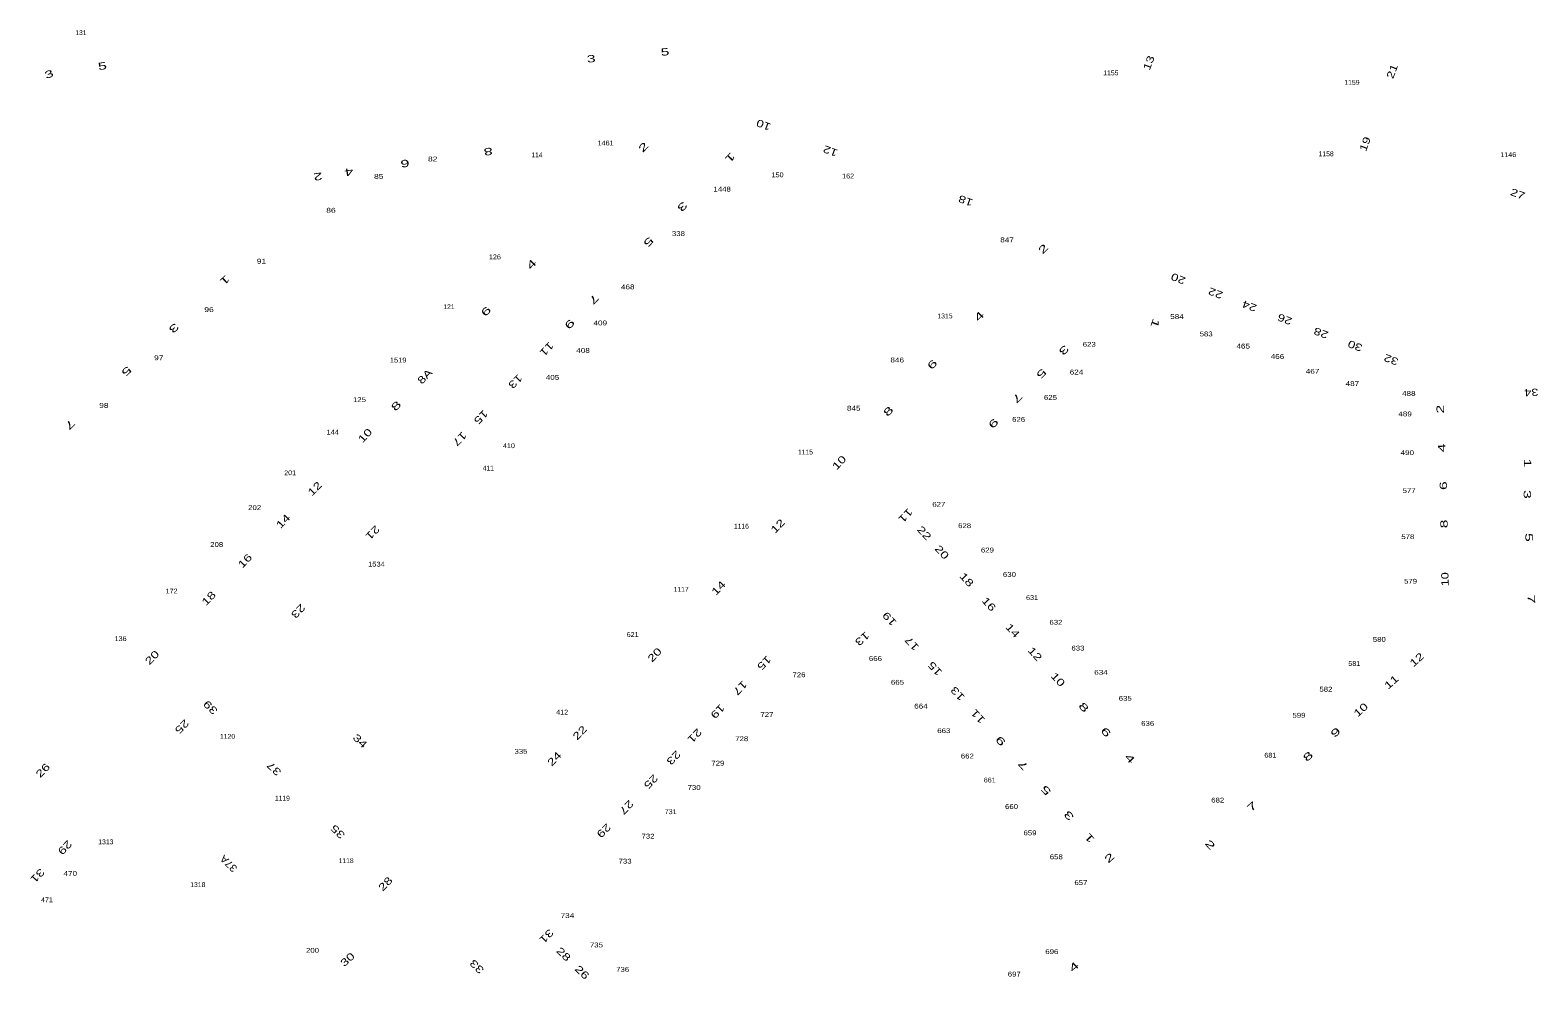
# Model space of a CAD drawing. Extents: x -828673 to -815583, y -1077737 to -1063807.
# Drawn here: x -819548.1 to -819237.8, y -1069104.1 to -1068908.7 of the extents above; entities that cross this region are included whole.
import ezdxf
from ezdxf.enums import TextEntityAlignment as Align

# ---------------------------------------------------------------- set-up
doc = ezdxf.new("R2010")
doc.units = 0
doc.header["$LTSCALE"] = 0.4
doc.layers.add('1', color=7, linetype='Continuous')
doc.layers.add('2', color=7, linetype='Continuous')

msp = doc.modelspace()

# ---------------------------------------------------------------- texts
at = {"layer": '1'}
for s, p in [('131', (-819537.617, -1068909.747)), ('114', (-819443.78, -1068934.925)), ('121', (-819461.888, -1068966.194)), ('1115', (-819388.525, -1068996.117)), ('411', (-819453.794, -1068999.429)), ('1116', (-819401.717, -1069011.39)), ('1117', (-819414.11, -1069024.403)), ('1119', (-819496.165, -1069067.403)), ('1118', (-819483.043, -1069080.264))]:
    msp.add_text(s, height=1, dxfattribs=at).set_placement(p, align=Align.CENTER)
for s, width, p in [('1155', 1.05, (-819325.699, -1068918.037)), ('1159', 1.05, (-819276.089, -1068919.989)), ('1461', 1.1, (-819429.658, -1068932.476)), ('82', 1.3, (-819465.237, -1068935.77)), ('1158', 1.05, (-819281.404, -1068934.699)), ('1146', 1.1, (-819243.927, -1068934.868)), ('85', 1.3, (-819476.337, -1068939.359)), ('150', 1.1, (-819394.274, -1068939.026)), ('162', 1.1, (-819379.763, -1068939.277)), ('1448', 1.2, (-819405.677, -1068941.98)), ('86', 1.3, (-819486.171, -1068946.327)), ('338', 1.2, (-819414.676, -1068951.136)), ('847', 1.25, (-819347.062, -1068952.43)), ('91', 1.3, (-819500.461, -1068956.814)), ('126', 1.1, (-819452.434, -1068955.932)), ('468', 1.25, (-819425.104, -1068962.104)), ('96', 1.3, (-819511.261, -1068966.78)), ('409', 1.25, (-819430.75, -1068969.532)), ('1315', 1.05, (-819359.837, -1068968.094)), ('584', 1.25, (-819312.093, -1068968.217)), ('583', 1.2, (-819306.091, -1068971.794)), ('97', 1.3, (-819521.602, -1068976.704)), ('408', 1.25, (-819434.299, -1068975.188)), ('623', 1.2, (-819330.15, -1068973.939)), ('465', 1.25, (-819298.465, -1068974.309)), ('466', 1.25, (-819291.414, -1068976.442)), ('1519', 1.15, (-819472.344, -1068977.171)), ('846', 1.25, (-819369.661, -1068977.162)), ('624', 1.25, (-819332.774, -1068979.649)), ('467', 1.25, (-819284.198, -1068979.493)), ('405', 1.25, (-819440.581, -1068980.751)), ('487', 1.25, (-819275.999, -1068982.02)), ('125', 1.2, (-819480.311, -1068985.321)), ('625', 1.2, (-819338.12, -1068984.867)), ('488', 1.25, (-819264.392, -1068984.056)), ('98', 1.3, (-819532.9, -1068986.516)), ('845', 1.25, (-819378.612, -1068987.093)), ('489', 1.25, (-819265.155, -1068988.27)), ('144', 1.15, (-819485.806, -1068992.009)), ('626', 1.2, (-819344.679, -1068989.395)), ('410', 1.1, (-819449.554, -1068994.81)), ('490', 1.25, (-819264.696, -1068996.244)), ('201', 1.1, (-819494.571, -1069000.381)), ('577', 1.2, (-819264.335, -1069004.061)), ('202', 1.2, (-819501.872, -1069007.56)), ('627', 1.2, (-819361.098, -1069006.887)), ('628', 1.2, (-819355.785, -1069011.284)), ('578', 1.2, (-819264.597, -1069013.544)), ('208', 1.2, (-819509.681, -1069015.161)), ('629', 1.2, (-819351.095, -1069016.304)), ('1534', 1.15, (-819476.81, -1069019.2)), ('630', 1.2, (-819346.569, -1069021.325)), ('579', 1.2, (-819264.039, -1069022.732)), ('172', 1.1, (-819518.966, -1069024.747)), ('631', 1.1, (-819341.921, -1069026.091)), ('632', 1.2, (-819337.001, -1069031.177)), ('136', 1.1, (-819529.456, -1069034.545)), ('621', 1.1, (-819424.098, -1069033.705)), ('580', 1.2, (-819270.46, -1069034.709)), ('666', 1.2, (-819374.141, -1069038.643)), ('633', 1.2, (-819332.475, -1069036.493)), ('634', 1.25, (-819327.72, -1069041.481)), ('581', 1.1, (-819275.609, -1069039.664)), ('726', 1.2, (-819389.876, -1069041.983)), ('665', 1.2, (-819369.608, -1069043.532)), ('582', 1.2, (-819281.446, -1069044.948)), ('635', 1.2, (-819322.742, -1069046.845)), ('412', 1.1, (-819438.596, -1069049.678)), ('727', 1.2, (-819396.47, -1069050.179)), ('664', 1.25, (-819364.765, -1069048.446)), ('599', 1.2, (-819286.989, -1069050.329)), ('663', 1.2, (-819360.073, -1069053.496)), ('636', 1.2, (-819318.118, -1069051.996)), ('1120', 1.05, (-819507.445, -1069054.669)), ('728', 1.2, (-819401.644, -1069055.153)), ('335', 1.2, (-819447.076, -1069057.755)), ('729', 1.2, (-819406.558, -1069060.184)), ('662', 1.2, (-819355.229, -1069058.723)), ('681', 1.1, (-819292.882, -1069058.544)), ('730', 1.2, (-819411.453, -1069065.209)), ('661', 1.1, (-819350.623, -1069063.659)), ('660', 1.2, (-819346.134, -1069069.115)), ('682', 1.2, (-819303.705, -1069067.798)), ('731', 1.1, (-819416.272, -1069070.182)), ('732', 1.2, (-819420.937, -1069075.223)), ('659', 1.2, (-819342.329, -1069074.545)), ('1313', 1.05, (-819532.486, -1069076.391)), ('733', 1.2, (-819425.652, -1069080.365)), ('658', 1.2, (-819336.933, -1069079.476)), ('470', 1.25, (-819539.807, -1069082.902)), ('1318', 1.05, (-819513.57, -1069085.196)), ('657', 1.2, (-819331.861, -1069084.78)), ('471', 1.1, (-819544.613, -1069088.328)), ('734', 1.25, (-819437.514, -1069091.589)), ('735', 1.2, (-819431.554, -1069097.628)), ('200', 1.2, (-819489.961, -1069098.733)), ('696', 1.2, (-819337.847, -1069098.993)), ('736', 1.2, (-819426.152, -1069102.652)), ('697', 1.2, (-819345.573, -1069103.625))]:
    msp.add_text(s, height=1, dxfattribs=dict(at, width=width)).set_placement(p, align=Align.CENTER)
at = {"layer": '2'}
for s, rotation, width, p in [('5', 5.425, 1.6, (-819417.3664, -1068913.9566)), ('5', 7.722, 1.65, (-819533.1038, -1068916.8569)), ('3', 5.685, 1.6, (-819432.5523, -1068915.3574)), ('13', 69.444, 1.35, (-819317.1964, -1068915.7358)), ('21', 69.621, 1.35, (-819267.116, -1068917.4737)), ('3', 22.395, 1.65, (-819543.9132, -1068918.4844)), ('10', 158.954, 1.35, (-819396.8772, -1068927.5522)), ('2', 46.135, 1.75, (-819421.3482, -1068933.3457)), ('19', 69.685, 1.35, (-819272.6885, -1068932.4399)), ('6', 188.398, 1.65, (-819471.0495, -1068935.453)), ('8', 188.033, 1.65, (-819453.9212, -1068932.9982)), ('1', 226.85, 1.75, (-819404.5498, -1068934.4776)), ('12', 159.773, 1.35, (-819383.1537, -1068932.9327)), ('2', 188.179, 1.65, (-819488.9413, -1068938.1536)), ('4', 188.305, 1.65, (-819482.5712, -1068937.2246)), ('27', 339.783, 1.35, (-819242.2482, -1068943.162)), ('3', 226.147, 1.75, (-819414.4016, -1068944.5644)), ('18', 159.866, 1.35, (-819355.3203, -1068943.1641)), ('5', 226.275, 1.75, (-819421.3612, -1068951.8371)), ('2', 46.072, 1.75, (-819339.0878, -1068954.3068)), ('4', 46.085, 1.75, (-819444.37, -1068957.4777)), ('1', 222.843, 1.75, (-819508.4975, -1068959.6834)), ('20', 158.728, 1.35, (-819311.5674, -1068959.2225)), ('22', 159.233, 1.35, (-819303.8936, -1068962.2121)), ('6', 45.964, 1.75, (-819453.7377, -1068967.1503)), ('7', 226.673, 1.75, (-819432.6014, -1068963.6539)), ('24', 159.259, 1.35, (-819296.9259, -1068964.8597)), ('3', 222.953, 1.75, (-819518.9895, -1068969.562)), ('9', 225.981, 1.75, (-819437.5935, -1068968.7533)), ('4', 46.228, 1.75, (-819352.2726, -1068968.1798)), ('1', 250.303, 1.65, (-819317.2808, -1068968.8422)), ('26', 159.177, 1.35, (-819289.6449, -1068967.5818)), ('28', 159.426, 1.35, (-819282.2014, -1068970.4048)), ('30', 159.11, 1.35, (-819275.1716, -1068973.053)), ('11', 227.023, 1.4, (-819442.3098, -1068973.9112)), ('3', 226.245, 1.75, (-819335.9002, -1068974.1293)), ('32', 159.358, 1.35, (-819267.7606, -1068975.9092)), ('5', 222.688, 1.75, (-819528.739, -1068978.4282)), ('6', 46.464, 1.75, (-819361.9095, -1068978.0941)), ('5', 226.348, 1.75, (-819340.5252, -1068978.9548)), ('8A', 45.794, 1.35, (-819466.3151, -1068980.5754)), ('13', 226.012, 1.4, (-819448.7413, -1068980.5711)), ('7', 225.898, 1.75, (-819345.4803, -1068983.973)), ('34', 182.252, 1.3, (-819239.206, -1068982.5962)), ('8', 45.789, 1.75, (-819472.2396, -1068986.6295)), ('15', 225.834, 1.4, (-819455.8324, -1068987.9044)), ('8', 46.252, 1.75, (-819370.9544, -1068987.7431)), ('2', 91.381, 1.6, (-819257.1949, -1068986.7681)), ('7', 223.57, 1.75, (-819540.3711, -1068989.4305)), ('10', 46.589, 1.4, (-819478.6128, -1068992.7279)), ('9', 226.212, 1.75, (-819350.3977, -1068989.192)), ('17', 226.185, 1.4, (-819460.2258, -1068992.3993)), ('4', 91.985, 1.6, (-819256.8715, -1068994.7415)), ('10', 46.367, 1.4, (-819381.0584, -1068998.306)), ('1', 271.366, 1.6, (-819240.7093, -1068997.8916)), ('12', 46.062, 1.4, (-819488.9776, -1069003.6799)), ('6', 91.184, 1.6, (-819256.5378, -1069002.5275)), ('3', 271.469, 1.6, (-819240.7457, -1069004.3638)), ('14', 45.999, 1.4, (-819495.4723, -1069010.39)), ('12', 46.221, 1.4, (-819393.7147, -1069011.3799)), ('11', 226.5, 1.4, (-819368.4612, -1069008.1797)), ('8', 91.23, 1.6, (-819256.4075, -1069010.4036)), ('21', 226.192, 1.4, (-819478.1156, -1069011.6933)), ('22', 312.752, 1.4, (-819364.6501, -1069012.8009)), ('5', 271.536, 1.6, (-819240.3997, -1069013.2199)), ('20', 312.466, 1.4, (-819361.0123, -1069016.7386)), ('16', 46.157, 1.4, (-819503.3234, -1069018.54)), ('14', 46.244, 1.4, (-819405.8874, -1069024.1407)), ('18', 312.51, 1.4, (-819355.9205, -1069022.4057)), ('10', 91.197, 1.3, (-819256.2109, -1069021.7997)), ('18', 46.06, 1.4, (-819510.7946, -1069026.2689)), ('7', 272.012, 1.6, (-819239.9101, -1069025.9357)), ('23', 226.192, 1.4, (-819493.4426, -1069027.8633)), ('16', 312.466, 1.4, (-819351.3373, -1069027.4346)), ('19', 132.653, 1.4, (-819370.702, -1069029.4902)), ('14', 312.418, 1.4, (-819346.4512, -1069032.8826)), ('13', 221.797, 1.4, (-819377.3331, -1069033.5198)), ('17', 132.487, 1.4, (-819366.0943, -1069034.5796)), ('20', 45.802, 1.4, (-819522.4331, -1069038.4494)), ('20', 46.364, 1.4, (-819419.0373, -1069037.9011)), ('15', 226.336, 1.4, (-819397.5545, -1069038.5457)), ('12', 312.496, 1.4, (-819341.8599, -1069037.7058)), ('12', 41.971, 1.4, (-819262.2596, -1069038.9193)), ('15', 132.408, 1.4, (-819361.3505, -1069039.7293)), ('17', 226.005, 1.4, (-819402.5045, -1069043.6701)), ('13', 132.402, 1.4, (-819356.6834, -1069044.8812)), ('10', 312.51, 1.4, (-819337.1365, -1069042.9557)), ('11', 41.615, 1.4, (-819267.4791, -1069043.5434)), ('39', 135.729, 1.4, (-819510.4505, -1069047.6875)), ('19', 226.687, 1.4, (-819407.1389, -1069048.5205)), ('11', 132.365, 1.4, (-819352.4928, -1069049.5654)), ('8', 312.656, 1.75, (-819331.8243, -1069048.6793)), ('10', 41.943, 1.4, (-819273.7698, -1069049.2556)), ('25', 225.506, 1.4, (-819517.3544, -1069051.6489)), ('22', 46.233, 1.4, (-819434.4451, -1069053.9368)), ('21', 226.34, 1.4, (-819411.8523, -1069053.5247)), ('6', 312.41, 1.75, (-819327.2678, -1069053.7997)), ('9', 41.242, 1.75, (-819278.9834, -1069053.9147)), ('34', 315.751, 1.4, (-819480.7043, -1069055.6528)), ('9', 132.402, 1.75, (-819347.8311, -1069054.6202)), ('24', 46.292, 1.4, (-819439.6583, -1069059.3097)), ('23', 226.165, 1.4, (-819416.1934, -1069058.0591)), ('4', 312.455, 1.75, (-819322.3147, -1069059.2157)), ('8', 42.004, 1.75, (-819284.6484, -1069058.8426)), ('26', 46.029, 1.4, (-819544.9192, -1069061.6877)), ('37', 135.75, 1.4, (-819497.3727, -1069060.3061)), ('25', 226.34, 1.4, (-819420.8583, -1069062.9817)), ('7', 132.207, 1.75, (-819343.1893, -1069059.6184)), ('5', 132.325, 1.75, (-819338.498, -1069064.7965)), ('27', 226.437, 1.4, (-819425.9056, -1069068.2616)), ('7', 41.96, 1.75, (-819296.161, -1069069.1782)), ('3', 132.594, 1.75, (-819333.7888, -1069070.0061)), ('35', 135.75, 1.4, (-819484.2497, -1069073.2811)), ('29', 225.16, 1.4, (-819430.55, -1069073.0621)), ('1', 132.308, 1.75, (-819329.5438, -1069074.6393)), ('29', 226.322, 1.4, (-819541.4369, -1069076.5525)), ('2', 312.481, 1.75, (-819305.8348, -1069076.984)), ('37A', 135.583, 1.1, (-819506.7221, -1069079.8369)), ('2', 41.902, 1.75, (-819325.5124, -1069079.735)), ('31', 226.137, 1.4, (-819547.0777, -1069082.3513)), ('28', 45.718, 1.4, (-819474.4412, -1069085.0656)), ('31', 225.837, 1.4, (-819442.3493, -1069094.8135)), ('30', 41.889, 1.4, (-819482.2718, -1069100.6667)), ('28', 315.746, 1.4, (-819438.8264, -1069099.556)), ('33', 135.765, 1.4, (-819455.6493, -1069101.0631)), ('26', 315.752, 1.4, (-819435.0223, -1069103.2858)), ('4', 41.355, 1.75, (-819332.816, -1069102.1747))]:
    msp.add_text(s, height=1.5, rotation=rotation, dxfattribs=dict(at, width=width)).set_placement(p, align=Align.CENTER)

doc.saveas('drawing.dxf')
